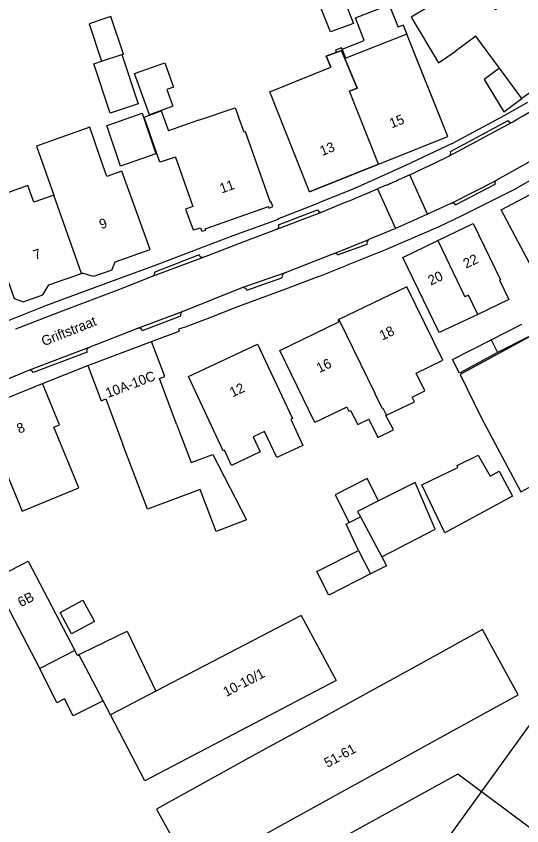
# Model space of a CAD drawing. Extents: x 194485 to 197793, y 468269 to 470822.
# Drawn here: x 194570.5 to 194632.2, y 469827.1 to 469925.9 of the extents above; entities that cross this region are included whole.
import ezdxf

# ---------------------------------------------------------------- set-up
doc = ezdxf.new("R2010")
doc.units = 0
for name, color, linetype in [('BGT grensvlak gebouwinstallatie plus 1', 7, 'Continuous'), ('BGT grensvlak overig bouwwerk uitbreiding populatie', 7, 'Continuous'), ('BGT grensvlak pand min 1', 7, 'Continuous'), ('BGT grensvlak pand op maaiveld', 7, 'Continuous'), ('BGT grensvlak pand op maaiveld LR', 7, 'Continuous'), ('BGT grensvlak wegdeel', 7, 'Continuous'), ('BGT tekst huisnummerreeks', 7, 'Continuous'), ('BGT tekst openbare ruimte label weg', 7, 'Continuous'), ('GEM grensvlak beperking object', 7, 'Continuous')]:
    doc.layers.add(name, color=color, linetype=linetype)

msp = doc.modelspace()

# ---------------------------------------------------------------- linework, layer by layer
at = {"layer": 'BGT grensvlak gebouwinstallatie plus 1'}
for p, q in [((194611.899, 469925.725), (194616.036, 469927.337)), ((194616.036, 469927.337), (194617.111, 469924.577)), ((194612.974, 469922.966), (194611.899, 469925.725)), ((194617.739, 469924.822), (194617.111, 469924.577)), ((194617.739, 469924.822), (194618.168, 469923.741)), ((194610.284, 469921.918), (194612.974, 469922.966)), ((194629.46, 469919.601), (194627.594, 469918.225)), ((194627.594, 469918.225), (194630, 469914.277)), ((194630, 469914.277), (194632.193, 469915.893)), ((194628.458, 469886.459), (194632.208, 469888.356)), ((194623.754, 469884.036), (194628.458, 469886.459)), ((194628.458, 469886.459), (194629.249, 469884.895)), ((194632.999, 469886.792), (194629.249, 469884.895)), ((194629.249, 469884.895), (194624.593, 469882.356)), ((194624.593, 469882.356), (194623.754, 469884.036)), ((194611.151, 469864.126), (194612.521, 469864.824)), ((194610.776, 469863.935), (194611.151, 469864.126)), ((194612.285, 469860.741), (194610.776, 469863.935)), ((194615.116, 469859.949), (194615.683, 469858.852)), ((194615.683, 469858.852), (194613.751, 469857.862)), ((194577.995, 469847.935), (194577.663, 469848.529)), ((194577.995, 469847.935), (194578.183, 469848.034)), ((194575.492, 469842.134), (194573.407, 469846.309)), ((194576.419, 469842.62), (194575.492, 469842.134)), ((194577.478, 469840.565), (194576.419, 469842.62)), ((194581.129, 469842.385), (194577.478, 469840.565))]:
    msp.add_line(p, q, dxfattribs=at)
msp.add_lwpolyline([(194614.736, 469866.772), (194613.338, 469869.519), (194609.421, 469867.526), (194611.151, 469864.126)], dxfattribs=at)
at = {"layer": 'BGT grensvlak overig bouwwerk uitbreiding populatie'}
for p, q in [((194582.081, 469925.884), (194579.429, 469925.003)), ((194579.429, 469925.003), (194580.948, 469920.428)), ((194583.601, 469921.309), (194582.081, 469925.884)), ((194583.397, 469921.241), (194583.601, 469921.309)), ((194575.89, 469853.149), (194578.666, 469854.66)), ((194578.666, 469854.66), (194580.058, 469852.054))]:
    msp.add_line(p, q, dxfattribs=at)
msp.add_lwpolyline([(194580.058, 469852.054), (194577.282, 469850.543), (194575.89, 469853.149)], dxfattribs=at)
at = {"layer": 'BGT grensvlak pand min 1'}
msp.add_lwpolyline([(194618.135, 469805.904), (194620.279, 469808.707), (194619.272, 469809.476), (194621.717, 469812.851), (194624.161, 469811.08), (194634.764, 469825.711), (194624.404, 469833.445), (194607.937, 469824.351), (194618.135, 469805.904)], dxfattribs=at)
at = {"layer": 'BGT grensvlak pand op maaiveld'}
for p, q in [((194618.168, 469923.741), (194610.73, 469920.809)), ((194619.603, 469920.158), (194618.168, 469923.741)), ((194580.948, 469920.428), (194583.397, 469921.241)), ((194610.73, 469920.809), (194610.284, 469921.918)), ((194606.396, 469918.685), (194608.898, 469919.695)), ((194632.193, 469915.893), (194629.46, 469919.601)), ((194601.451, 469916.688), (194606.396, 469918.685)), ((194606.302, 469904.492), (194601.451, 469916.688)), ((194592.749, 469913.238), (194589.095, 469911.951)), ((194606.302, 469904.492), (194614.724, 469907.874)), ((194582.18, 469894.94), (194582.591, 469895.958)), ((194578.502, 469894.527), (194578.588, 469894.556)), ((194579.964, 469894.187), (194578.588, 469894.556)), ((194582.18, 469894.94), (194579.964, 469894.187)), ((194626.836, 469889.524), (194622.123, 469887.32)), ((194579.253, 469883.312), (194587.016, 469886.253)), ((194565.358, 469877.686), (194573.731, 469881.102)), ((194615.629, 469877.211), (194615.69, 469877.24)), ((194616.531, 469875.447), (194615.629, 469877.211)), ((194586.543, 469865.754), (194583.539, 469873.683)), ((194614.736, 469866.772), (194612.177, 469865.47)), ((194612.177, 469865.47), (194612.521, 469864.824)), ((194612.521, 469864.824), (194615.116, 469859.949)), ((194612.285, 469860.741), (194613.751, 469857.862)), ((194613.751, 469857.862), (194608.662, 469855.272)), ((194573.407, 469846.309), (194567.719, 469857.215)), ((194605.277, 469852.787), (194587.546, 469843.546)), ((194605.277, 469852.787), (194609.541, 469844.855)), ((194578.531, 469848.204), (194584.044, 469850.888)), ((194584.044, 469850.888), (194587.546, 469843.546)), ((194577.663, 469848.529), (194573.407, 469846.309)), ((194578.183, 469848.034), (194578.531, 469848.204)), ((194581.129, 469842.385), (194578.183, 469848.034)), ((194609.541, 469844.855), (194586.216, 469832.619)), ((194582.024, 469840.669), (194581.129, 469842.385)), ((194586.216, 469832.619), (194582.024, 469840.669))]:
    msp.add_line(p, q, dxfattribs=at)
for points in [[(194620.802, 469927.082), (194627.121, 469930.805), (194627.301, 469930.645), (194626.781, 469930.294), (194628.962, 469926.744), (194629.832, 469927.265), (194629.151, 469928.325), (194632.391, 469930.607), (194639.402, 469921.067), (194632.193, 469915.893)], [(194607.594, 469927.153), (194610.421, 469928.268), (194611.675, 469925.064), (194608.87, 469924.032), (194607.594, 469927.153)], [(194620.802, 469927.082), (194618.696, 469925.816), (194622.051, 469920.242), (194624.072, 469921.642)], [(194629.46, 469919.601), (194626.592, 469923.493), (194624.072, 469921.642)], [(194610.284, 469921.918), (194610.22, 469922.081), (194609.458, 469921.78), (194609.558, 469921.508)], [(194583.397, 469921.241), (194585.395, 469915.221), (194581.984, 469914.089)], [(194609.558, 469921.508), (194608.33, 469921.054), (194608.898, 469919.695)], [(194581.984, 469914.089), (194579.986, 469920.108), (194580.948, 469920.428)], [(194586.772, 469913.916), (194584.972, 469918.924), (194588.645, 469920.248), (194589.713, 469917.286), (194588.909, 469916.996), (194589.64, 469914.95), (194586.772, 469913.916)], [(194614.724, 469907.874), (194623.163, 469911.264), (194619.603, 469920.158)], [(194589.942, 469908.744), (194588.041, 469908.113), (194586.141, 469913.603), (194588.204, 469914.369), (194589.095, 469911.951)], [(194592.749, 469913.238), (194597.242, 469914.761), (194597.633, 469913.658)], [(194585.886, 469914.081), (194587.558, 469909.13), (194583.262, 469907.647), (194581.591, 469912.598), (194582.541, 469912.926), (194585.886, 469914.081)], [(194589.942, 469908.744), (194592.082, 469902.696), (194591.184, 469902.39), (194592.114, 469899.859), (194592.987, 469900.09), (194593.165, 469899.691), (194593.652, 469899.807), (194593.588, 469899.982), (194601.282, 469902.696), (194601.333, 469902.509), (194601.819, 469902.712), (194601.64, 469903.261), (194601.553, 469903.21), (194598.508, 469911.839), (194598.314, 469911.769), (194597.633, 469913.658)], [(194580.869, 469908.433), (194579.492, 469912.378), (194572.983, 469910.079), (194575.105, 469904.1)], [(194582.591, 469895.958), (194586.88, 469897.474), (194583.429, 469907.038), (194581.583, 469906.388), (194580.869, 469908.433)], [(194575.105, 469904.1), (194572.68, 469903.24), (194571.941, 469905.285), (194567.951, 469903.833), (194568.627, 469901.801), (194566.844, 469901.189), (194570.272, 469891.475), (194571.387, 469891.07), (194573.781, 469891.924), (194574.498, 469893.153), (194578.502, 469894.527)], [(194637.516, 469897.768), (194634.241, 469896.018), (194635.108, 469894.384), (194634.157, 469893.876), (194629.691, 469902.292), (194633.909, 469904.54)], [(194621.976, 469898.567), (194626.265, 469900.631), (194629.589, 469893.776), (194629.49, 469893.728), (194630.635, 469891.368), (194626.836, 469889.524)], [(194622.123, 469887.32), (194617.687, 469896.503), (194621.976, 469898.567)], [(194619.315, 469882.38), (194622.549, 469883.963), (194618.19, 469892.902), (194609.888, 469888.904)], [(194639.918, 469890.689), (194637.893, 469889.611), (194640.754, 469884.292), (194636.37, 469881.911), (194633.512, 469886.992), (194624.677, 469882.189), (194627.234, 469876.949), (194632.08, 469867.902), (194645.747, 469875.334), (194644.802, 469877.108), (194652.498, 469881.219)], [(194610.843, 469878.234), (194606.965, 469876.335), (194602.703, 469885.148), (194609.898, 469888.647)], [(194609.888, 469888.904), (194609.794, 469888.859), (194609.898, 469888.647)], [(194590.096, 469876.167), (194587.997, 469881.708), (194588.645, 469881.954), (194587.016, 469886.253)], [(194591.528, 469881.95), (194599.965, 469885.927), (194604.214, 469876.854), (194604.015, 469876.761), (194605.504, 469873.561), (194602.331, 469872.084), (194600.833, 469875.267), (194599.43, 469874.608), (194600.288, 469872.757), (194596.804, 469871.113), (194595.95, 469872.975), (194595.787, 469872.898), (194591.528, 469881.95)], [(194579.253, 469883.312), (194580.882, 469879.013), (194581.44, 469879.224), (194583.539, 469873.683)], [(194615.69, 469877.24), (194619.119, 469878.856), (194618.833, 469879.431), (194620.375, 469880.205), (194619.315, 469882.38)], [(194565.358, 469877.686), (194567.448, 469872.624), (194568.169, 469872.922), (194571.24, 469865.511), (194578.158, 469868.386), (194575.107, 469875.782), (194575.8, 469876.068), (194573.731, 469881.102)], [(194610.843, 469878.234), (194611.11, 469877.747), (194611.323, 469877.811), (194612.186, 469876.092)], [(194612.186, 469876.092), (194613.53, 469876.75), (194614.625, 469874.513), (194616.531, 469875.447)], [(194590.096, 469876.167), (194591.878, 469871.464), (194594.496, 469872.456), (194598.625, 469864.454), (194594.916, 469863.049), (194592.969, 469868.189), (194586.543, 469865.754)], [(194629.457, 469870.431), (194631.054, 469867.37), (194622.824, 469862.88), (194619.988, 469868.728), (194624.414, 469870.874), (194624.298, 469871.112), (194626.891, 469872.369), (194626.93, 469872.274)], [(194626.93, 469872.274), (194628.358, 469869.797), (194629.457, 469870.431)], [(194615.116, 469859.949), (194621.624, 469863.349), (194619.208, 469869.048), (194614.736, 469866.772)], [(194608.662, 469855.272), (194607.197, 469858.151), (194612.285, 469860.741)], [(194567.719, 469857.215), (194571.975, 469859.434), (194577.663, 469848.529)], [(194587.635, 469829.176), (194587.897, 469828.702), (194592.024, 469821.228), (194597.966, 469824.501), (194604.44, 469828.066), (194611.442, 469831.922), (194617.572, 469835.298), (194624.293, 469839), (194631.755, 469843.11), (194628.273, 469849.498), (194627.409, 469851.082), (194619.913, 469846.953), (194613.191, 469843.251), (194607.062, 469839.875), (194600.059, 469836.019), (194593.586, 469832.454), (194587.635, 469829.176)], [(194637.918, 469838.708), (194637.525, 469838.993), (194634.451, 469841.226), (194629.173, 469833.937), (194625.244, 469828.51), (194620.861, 469822.458), (194616.594, 469816.564), (194624.161, 469811.08), (194631.833, 469805.519)]]:
    msp.add_lwpolyline(points, dxfattribs=at)
at = {"layer": 'BGT grensvlak pand op maaiveld LR'}
for p, q in [((194609.558, 469921.508), (194610.213, 469921.75)), ((194610.213, 469921.75), (194612.132, 469917.162)), ((194612.132, 469917.162), (194611.195, 469916.786)), ((194614.724, 469907.874), (194611.195, 469916.786)), ((194578.502, 469894.527), (194575.105, 469904.1)), ((194621.976, 469898.567), (194625.263, 469891.695)), ((194609.888, 469888.904), (194614.286, 469879.919)), ((194615.214, 469878.024), (194614.286, 469879.919)), ((194615.285, 469878.059), (194615.214, 469878.024)), ((194615.69, 469877.24), (194615.285, 469878.059)), ((194587.546, 469843.546), (194582.024, 469840.669))]:
    msp.add_line(p, q, dxfattribs=at)
msp.add_lwpolyline([(194626.836, 469889.524), (194625.683, 469891.897), (194625.263, 469891.695)], dxfattribs=at)
at = {"layer": 'BGT grensvlak wegdeel'}
for p, q in [((194630.112, 469913.856), (194632.922, 469915.437)), ((194623.509, 469909.434), (194630.531, 469913.193)), ((194623.692, 469910.395), (194630.112, 469913.856)), ((194623.319, 469908.851), (194631.018, 469912.983)), ((194631.018, 469912.983), (194631.119, 469913.037)), ((194635.27, 469909.343), (194629.107, 469905.912)), ((194618.531, 469906.589), (194617.52, 469906.132)), ((194620.693, 469901.777), (194618.531, 469906.589)), ((194615.648, 469905.304), (194614.599, 469904.851)), ((194623.556, 469903.092), (194629.062, 469905.889)), ((194624.128, 469902.932), (194628.932, 469905.447)), ((194629.062, 469905.889), (194629.107, 469905.912)), ((194614.599, 469904.851), (194616.808, 469900.046)), ((194607.76, 469902.035), (194610.785, 469903.265)), ((194630.087, 469904.166), (194624.788, 469901.55)), ((194602.448, 469901.206), (194607.424, 469903.169)), ((194602.532, 469900.482), (194607.28, 469902.312)), ((194623.556, 469903.092), (194620.693, 469901.777)), ((194602.324, 469899.93), (194607.76, 469902.035)), ((194620.693, 469901.777), (194618.178, 469900.623)), ((194618.178, 469900.623), (194616.808, 469900.046)), ((194598.849, 469898.628), (194602.324, 469899.93)), ((194616.808, 469900.046), (194613.555, 469898.677)), ((194593.37, 469896.547), (194598.849, 469898.628)), ((194609.332, 469896.991), (194613.555, 469898.677)), ((194609.731, 469896.795), (194613.351, 469898.116)), ((194615.586, 469897.437), (194613.545, 469896.604)), ((194587.16, 469894.216), (194593.37, 469896.547)), ((194592.826, 469896.794), (194587.43, 469894.712)), ((194603.395, 469894.675), (194609.272, 469896.967)), ((194609.272, 469896.967), (194609.332, 469896.991)), ((194613.545, 469896.604), (194610.709, 469895.472)), ((194607.451, 469894.176), (194610.709, 469895.472)), ((194598.097, 469892.808), (194603.395, 469894.675)), ((194582.842, 469892.511), (194587.16, 469894.216)), ((194598.662, 469892.519), (194602.933, 469894.024)), ((194576.391, 469890.056), (194582.842, 469892.511)), ((194590.815, 469889.909), (194598.097, 469892.808)), ((194570.474, 469887.762), (194576.391, 469890.056)), ((194585.353, 469887.843), (194590.815, 469889.909)), ((194585.93, 469887.595), (194590.628, 469889.364)), ((194579.34, 469885.492), (194585.353, 469887.843)), ((194587.016, 469886.253), (194590.415, 469887.5)), ((194572.087, 469882.726), (194579.34, 469885.492)), ((194579.165, 469884.946), (194572.6, 469882.44)), ((194565.014, 469879.865), (194572.087, 469882.726)), ((194573.731, 469881.102), (194579.253, 469883.312))]:
    msp.add_line(p, q, dxfattribs=at)
for points in [[(194623.692, 469910.395), (194617.924, 469907.687), (194611.789, 469904.923), (194607.424, 469903.169)], [(194637.163, 469908.227), (194636.609, 469907.844), (194631.304, 469904.791), (194630.087, 469904.166)], [(194624.788, 469901.55), (194622.073, 469900.229), (194615.586, 469897.437)], [(194602.448, 469901.206), (194602.477, 469901.127), (194596.931, 469899.137), (194590.962, 469896.861), (194587.68, 469895.574)], [(194587.68, 469895.574), (194580.049, 469892.776), (194574.102, 469890.585), (194569.645, 469888.816), (194567.427, 469887.873), (194564.84, 469886.854)], [(194607.451, 469894.176), (194603.37, 469892.607), (194597.204, 469890.333), (194594.668, 469889.325), (194591.118, 469887.992), (194590.308, 469887.729), (194590.415, 469887.5)]]:
    msp.add_lwpolyline(points, dxfattribs=at)
for centre, radius, start, end in [((194543.182, 470060.049), 171.305, 300.88637, 304.72798), ((194630.886, 469913.348), 0.388, 203.51878, 289.8287), ((194623.066, 469909.256), 0.477, 301.98762, 21.91075), ((194541.237, 470076.397), 186.572, 294.47437, 296.10064), ((194549.288, 470057.866), 166.37, 293.5077, 294.21265), ((194629.238, 469905.597), 0.341, 121.12024, 206.10068), ((194536.655, 470086.912), 198.044, 291.9818, 293.17684), ((194607.658, 469902.413), 0.392, 195.00066, 285.02228), ((194623.753, 469902.694), 0.444, 32.36705, 116.37818), ((194602.153, 469900.31), 0.416, 294.26839, 24.43763), ((194613.752, 469898.288), 0.436, 116.82184, 203.21195), ((194593.228, 469896.958), 0.434, 202.12211, 289.0376), ((194609.424, 469896.674), 0.33, 21.49494, 106.18193), ((194586.992, 469894.629), 0.446, 292.14374, 10.73251), ((194603.653, 469894.003), 0.72, 110.98101, 178.29407), ((194598.202, 469892.317), 0.502, 23.7301, 102.09001), ((194590.979, 469889.548), 0.396, 114.39123, 207.7326), ((194585.486, 469887.358), 0.503, 28.14112, 105.34191), ((194579.502, 469885.139), 0.388, 114.65948, 209.79788), ((194572.206, 469882.336), 0.408, 14.82218, 106.89806)]:
    msp.add_arc(centre, radius, start, end, dxfattribs=at)
at = {"layer": 'GEM grensvlak beperking object'}
for points in [[(194614.724, 469907.874), (194623.163, 469911.264), (194618.168, 469923.741), (194610.73, 469920.809), (194610.22, 469922.081), (194609.458, 469921.78), (194609.558, 469921.508)], [(194614.724, 469907.874), (194606.302, 469904.492), (194601.451, 469916.688), (194608.898, 469919.695), (194608.33, 469921.054), (194609.558, 469921.508)], [(194614.724, 469907.874), (194611.195, 469916.786), (194612.132, 469917.162), (194610.213, 469921.75), (194609.558, 469921.508)]]:
    msp.add_lwpolyline(points, dxfattribs=at)

# ---------------------------------------------------------------- texts
at = {"layer": 'BGT tekst huisnummerreeks'}
for s, rotation, p in [('15', 21.3, (194616.326, 469912.239)), ('13', 22.1, (194607.859, 469908.864)), ('11', 19.4, (194595.587, 469904.293)), ('9', 18.8, (194580.89, 469899.923)), ('7', 18.9, (194572.842, 469896.18)), ('22', 25.7, (194625.403, 469895.111)), ('20', 25.7, (194621.11, 469893.046)), ('18', 25.7, (194615.181, 469886.348)), ('16', 25.9, (194607.508, 469882.37)), ('10A-10C', 20.7, (194581.701, 469879.323)), ('12', 25.2, (194596.904, 469879.399)), ('8', 22.2, (194570.885, 469874.972)), ('6B', 27.5, (194571.103, 469853.793)), ('10-10/1', 27.5, (194596.153, 469842.846)), ('51-61', 28.8, (194608.506, 469834.189))]:
    msp.add_text(s, height=1.2, rotation=rotation, dxfattribs=at).set_placement(p)
at = {"layer": 'BGT tekst openbare ruimte label weg'}
msp.add_text('Griftstraat', height=1.2, rotation=21.8, dxfattribs=at).set_placement((194573.887, 469885.647))

doc.saveas('drawing.dxf')
